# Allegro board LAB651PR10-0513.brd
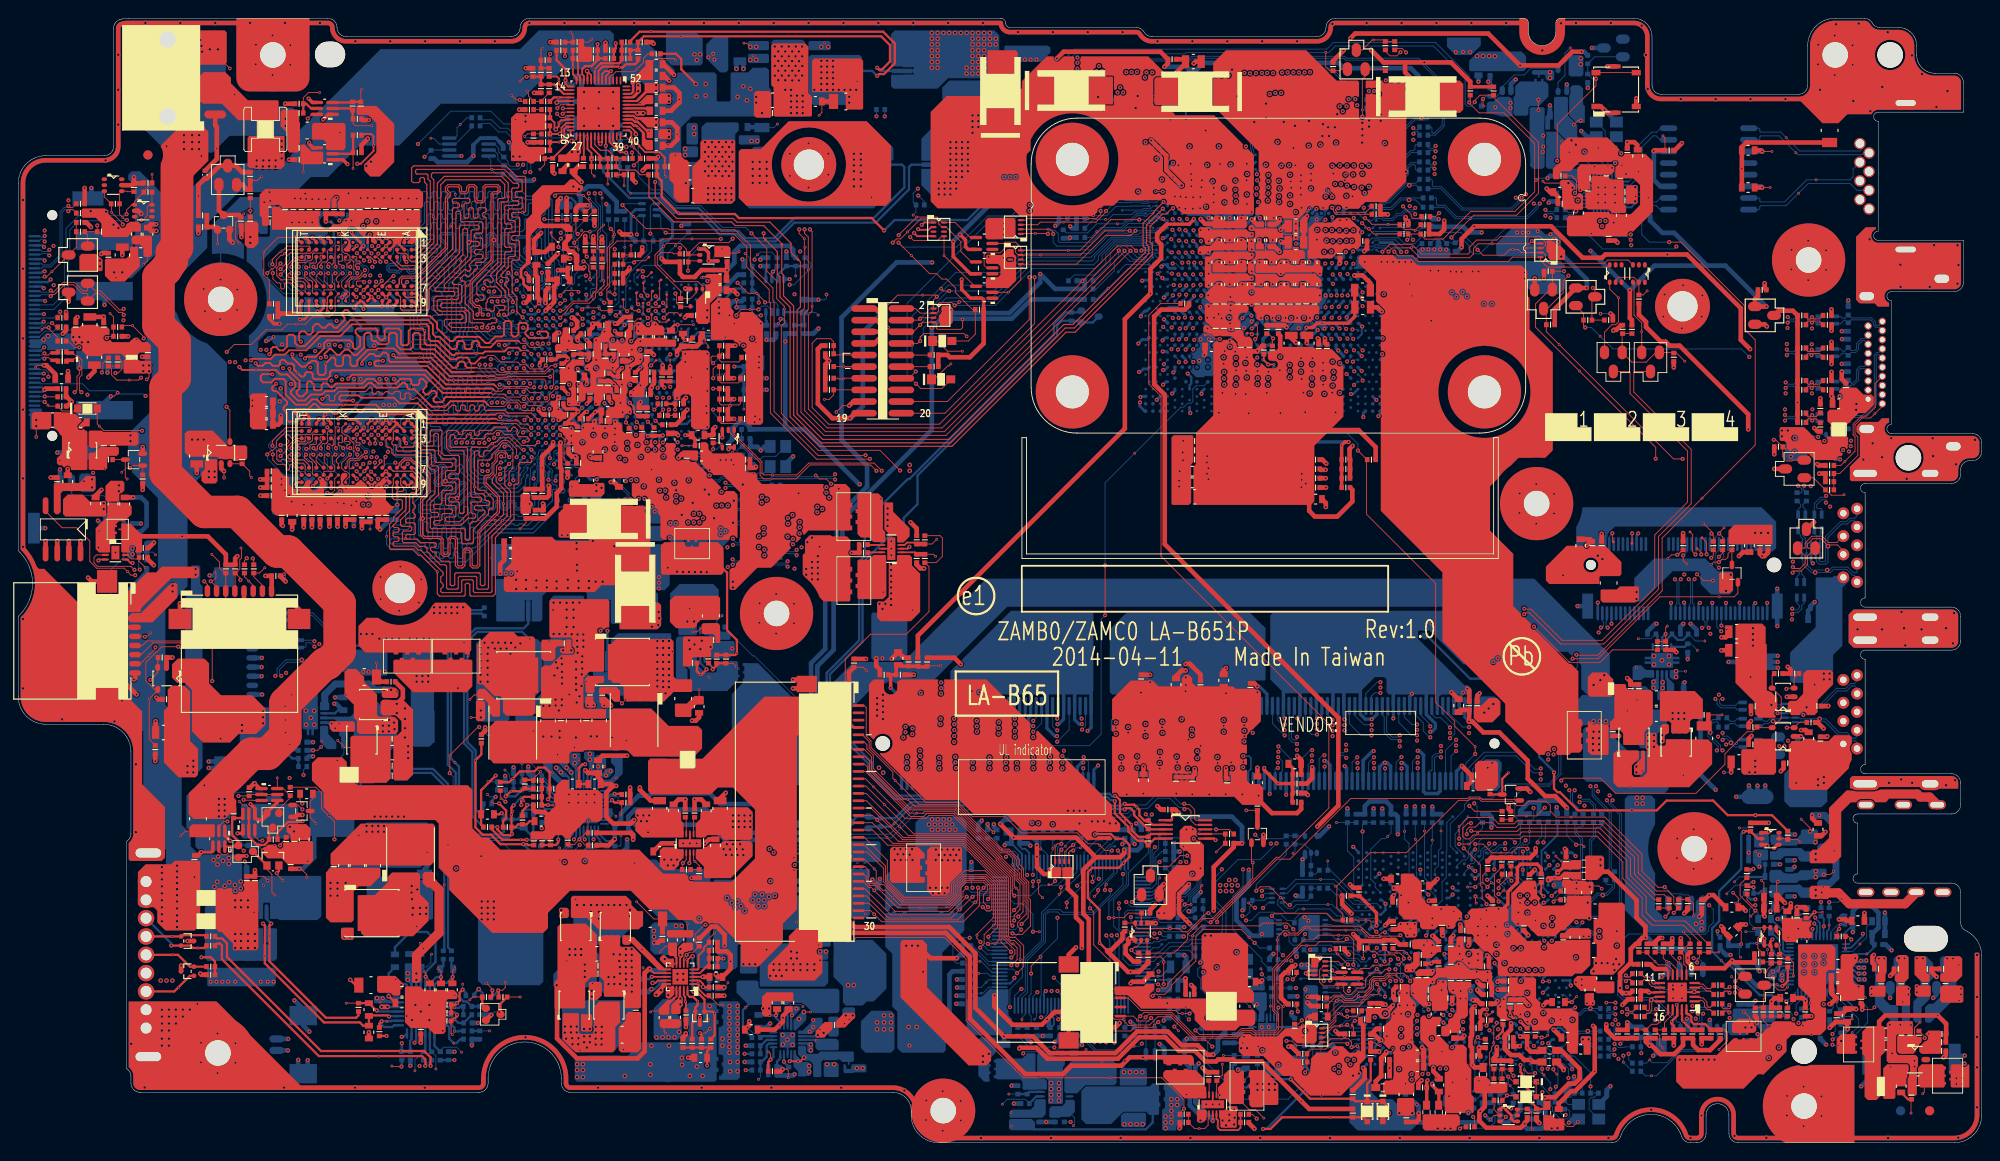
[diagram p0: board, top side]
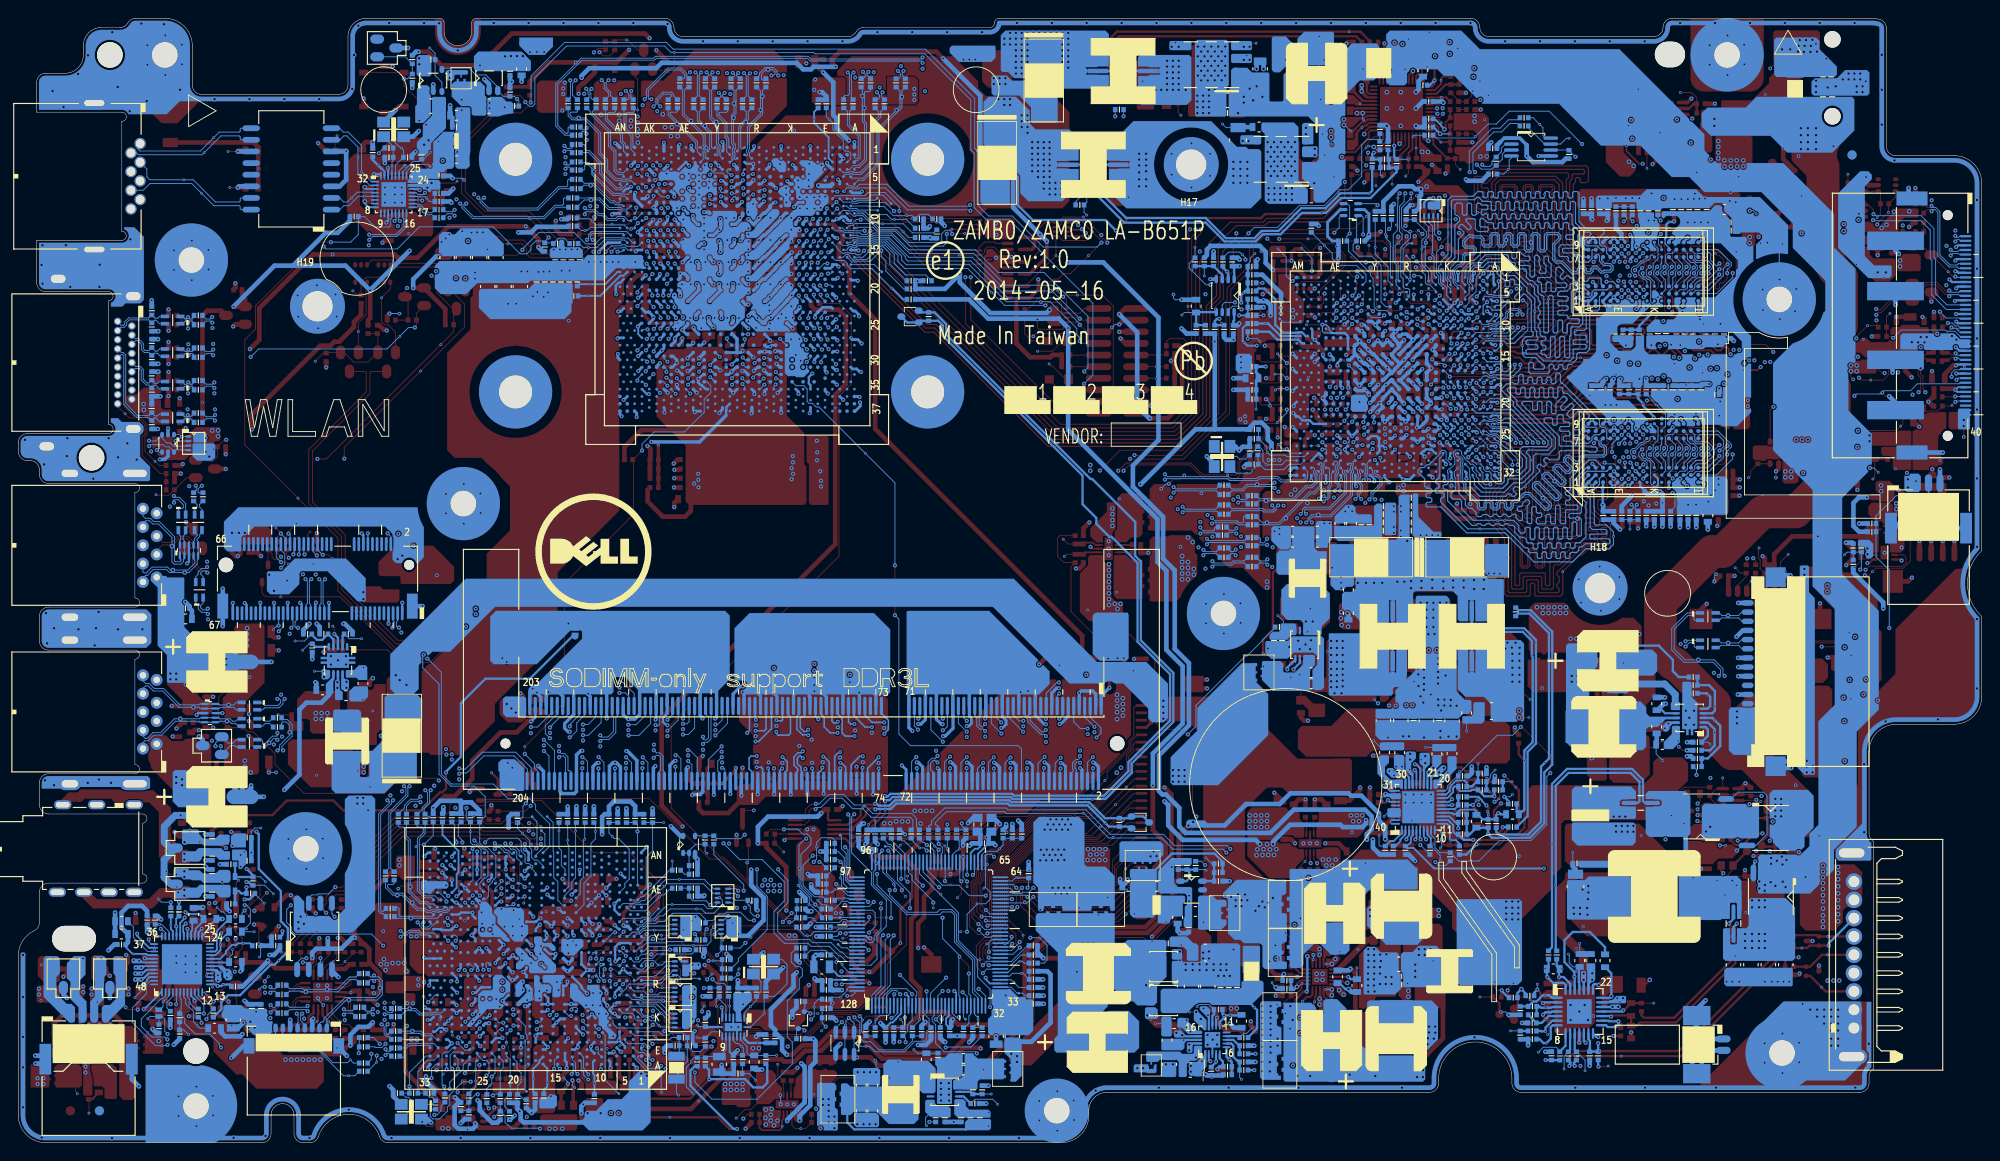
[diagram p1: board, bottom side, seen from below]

Outline 214.4 x 122.8 mm; copper layers: TOP, GND1, IN1, VCC, IN2, IN3, GND2, BOTTOM. Coordinates in mm from the lower left corner of the outline.
Outline path: 0,104.8 arc(0.88,106.92) 3,107.8 9.4,107.8 arc(10.11,108.09) 10.4,108.8 10.4,121.71 arc(10.59,122.3) 11.1,122.66 arc(11.54,122.77) 12,122.8 33.8,122.8 arc(34.51,122.51) 34.8,121.8 arc(35.09,121.09) 35.8,120.8 53.8,120.8 arc(54.51,121.09) 54.8,121.8 arc(55.09,122.51) 55.8,122.8 107.3,122.8 arc(107.65,122.65) 107.8,122.3 arc(107.95,121.95) 108.3,121.8 122.07,121.8 arc(122.57,121.67) 122.93,121.3 arc(123.3,120.93) 123.8,120.8 141.8,120.8 arc(142.51,121.09) 142.8,121.8 arc(143.09,122.51) 143.8,122.8 164.4,122.8 arc(164.75,122.65) 164.9,122.3 164.9,121.3 arc(166.4,119.8) 167.9,121.3 167.9,122.3 arc(168.05,122.65) 168.4,122.8 176.4,122.8 arc(177.81,122.21) 178.4,120.8 178.4,115.5 arc(178.69,114.79) 179.4,114.5 194.4,114.5 arc(195.11,114.79) 195.4,115.5 195.4,119.8 arc(196.28,121.92) 198.4,122.8 201.57,122.8 arc(202.07,122.67) 202.43,122.3 arc(202.8,121.93) 203.3,121.8 205.3,121.8 arc(206.71,121.21) 207.3,119.8 207.3,118.8 arc(207.89,117.39) 209.3,116.8 211.4,116.8 arc(212.11,116.51) 212.4,115.8 212.4,112.55 203.1,112.55 arc(202.6,112.05) 203.1,111.55 203.1,99.55 arc(202.6,99.05) 203.1,98.55 212.4,98.55 212.4,93.95 arc(212.11,93.24) 211.4,92.95 204.55,92.95 arc(204.05,92.45) 204.55,91.95 204.55,78.45 arc(204.05,77.95) 204.55,77.45 213.4,77.45 arc(214.11,77.16) 214.4,76.45 214.4,75.5 arc(214.11,74.79) 213.4,74.5 213.1,74.5 arc(212.39,74.2) 212.1,73.5 212.1,73 arc(211.81,72.29) 211.1,72 201.67,72 arc(201.17,71.5) 201.67,71 201.67,59.5 arc(201.17,59) 201.67,58.5 211.1,58.5 arc(211.81,58.2) 212.1,57.5 212.1,54.8 arc(211.81,54.09) 211.1,53.8 201.67,53.8 arc(201.17,53.3) 201.67,52.8 201.67,41.3 arc(201.17,40.8) 201.67,40.3 211.1,40.3 arc(211.81,40) 212.1,39.3 212.1,36.9 arc(211.81,36.19) 211.1,35.9 200.85,35.9 arc(200.35,35.4) 200.85,34.9 200.85,29.35 arc(200.35,28.85) 200.85,28.35 211.1,28.35 arc(211.81,28.06) 212.1,27.35 212.1,24.05 arc(212.26,23.52) 212.67,23.15 arc(213.93,22.04) 214.4,20.43 214.4,3 arc(213.52,0.88) 211.4,0 187.8,0 arc(187.09,0.29) 186.8,1 186.8,3 arc(185.55,4.25) 184.3,3 184.3,1 arc(184.01,0.29) 183.3,0 182.58,0 arc(181.99,0.19) 181.63,0.69 arc(178.3,3.1) 174.97,0.69 arc(174.61,0.19) 174.02,0 100.5,0 arc(98.38,0.88) 97.5,3 97.5,3.5 arc(96.91,4.91) 95.5,5.5 60.3,5.5 arc(59.59,5.79) 59.3,6.5 59.3,7 arc(55.3,11) 51.3,7 51.3,6.5 arc(51.01,5.79) 50.3,5.5 13.3,5.5 arc(12.59,5.79) 12.3,6.5 12.3,7.23 arc(12.17,7.73) 11.8,8.1 11.8,32.9 arc(12.17,33.27) 12.3,33.77 12.3,42.7 arc(11.42,44.82) 9.3,45.7 3,45.7 arc(0.88,46.58) 0,48.7 0,57.49 arc(1.55,61.07) 0,64.65 0,104.8

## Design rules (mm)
net group 11/16: nets USB20_MINI_N1 USB20_MINI_P1
net group 21: nets +FBA_VREF2 +FBA_VREF3
net group APU_DP2_0: nets APU_DP2_N0 APU_DP2_P0
net group APU_DP2_1: nets APU_DP2_N1 APU_DP2_P1
net group APU_DP2_2: nets APU_DP2_N2 APU_DP2_P2
net group APU_DP2_3: nets APU_DP2_N3 APU_DP2_P3
net group CSI: nets CSIN CSIP
net group DDR_8/12_25: nets MEM_MA_EVENT# MEM_MA_RST#
net group DIFFPAIR3: nets EC_SMB_CK1_R EC_SMB_DA1_R
net group DP2_TX0_R: nets DP2_TXN0_R DP2_TXP0_R
net group DP2_TX1_R: nets DP2_TXN1_R DP2_TXP1_R
net group DP2_TX2_R: nets DP2_TXN2_R DP2_TXP2_R
net group DP2_TX3_R: nets DP2_TXN3_R DP2_TXP3_R
net group FCH_S0: nets FCH_SCLK0 FCH_SDATA0
net group FCH_S1: nets FCH_SCLK1 FCH_SDATA1
net group FCH_S1-TP: nets FCH_SCLK1_TP FCH_SDATA1_TP
net group FCH_S4: nets FCH_SCLK4 FCH_SDATA4
net group ISEN1: nets ISEN1N ISEN1P
net group ISENA1: nets ISENA1N ISENA1P
net group MDI0: nets MDI0+ MDI0-
net group MDI1: nets MDI1+ MDI1-
net group MDO0: nets MDO0+ MDO0-
net group MDO1: nets MDO1+ MDO1-
net group PCIE_CALR: nets PCIE_CALRN PCIE_CALRP
net group PCIE_PRX_DTX_0: nets PCIE_PRX_DTX_N0 PCIE_PRX_DTX_P0
net group PCIE_PRX_DTX_0_C: nets PCIE_PRX_DTX_N0_C PCIE_PRX_DTX_P0_C
net group PCIE_PRX_DTX_1: nets PCIE_PRX_DTX_N1 PCIE_PRX_DTX_P1
net group PCIE_PTX_C_DRX_0: nets PCIE_PTX_C_DRX_N0 PCIE_PTX_C_DRX_P0
net group PCIE_PTX_C_DRX_1: nets PCIE_PTX_C_DRX_N1 PCIE_PTX_C_DRX_P1
net group PCIE_PTX_DRX_0: nets PCIE_PTX_DRX_N0 PCIE_PTX_DRX_P0
net group PCIE_PTX_DRX_1: nets PCIE_PTX_DRX_N1 PCIE_PTX_DRX_P1
net group PEG_GTX_C_HRX_0: nets PEG_GTX_C_HRX_N0 PEG_GTX_C_HRX_P0
net group PEG_GTX_C_HRX_1: nets PEG_GTX_C_HRX_N1 PEG_GTX_C_HRX_P1
net group PEG_GTX_C_HRX_2: nets PEG_GTX_C_HRX_N2 PEG_GTX_C_HRX_P2
net group PEG_GTX_C_HRX_3: nets PEG_GTX_C_HRX_N3 PEG_GTX_C_HRX_P3
net group PEG_GTX_C_HRX_4: nets PEG_GTX_C_HRX_N4 PEG_GTX_C_HRX_P4
net group PEG_GTX_C_HRX_5: nets PEG_GTX_C_HRX_N5 PEG_GTX_C_HRX_P5
net group PEG_GTX_C_HRX_6: nets PEG_GTX_C_HRX_N6 PEG_GTX_C_HRX_P6
net group PEG_GTX_C_HRX_7: nets PEG_GTX_C_HRX_N7 PEG_GTX_C_HRX_P7
net group PEG_GTX_HRX_0: nets PEG_GTX_HRX_N0 PEG_GTX_HRX_P0
net group PEG_GTX_HRX_1: nets PEG_GTX_HRX_N1 PEG_GTX_HRX_P1
net group PEG_GTX_HRX_2: nets PEG_GTX_HRX_N2 PEG_GTX_HRX_P2
net group PEG_GTX_HRX_3: nets PEG_GTX_HRX_N3 PEG_GTX_HRX_P3
net group PEG_GTX_HRX_4: nets PEG_GTX_HRX_N4 PEG_GTX_HRX_P4
net group PEG_GTX_HRX_5: nets PEG_GTX_HRX_N5 PEG_GTX_HRX_P5
net group PEG_GTX_HRX_6: nets PEG_GTX_HRX_N6 PEG_GTX_HRX_P6
net group PEG_GTX_HRX_7: nets PEG_GTX_HRX_N7 PEG_GTX_HRX_P7
net group PEG_HTX_C_GRX_0: nets PEG_HTX_C_GRX_N0 PEG_HTX_C_GRX_P0
net group PEG_HTX_C_GRX_1: nets PEG_HTX_C_GRX_N1 PEG_HTX_C_GRX_P1
net group PEG_HTX_C_GRX_2: nets PEG_HTX_C_GRX_N2 PEG_HTX_C_GRX_P2
net group PEG_HTX_C_GRX_3: nets PEG_HTX_C_GRX_N3 PEG_HTX_C_GRX_P3
net group PEG_HTX_C_GRX_4: nets PEG_HTX_C_GRX_N4 PEG_HTX_C_GRX_P4
net group PEG_HTX_C_GRX_5: nets PEG_HTX_C_GRX_N5 PEG_HTX_C_GRX_P5
net group PEG_HTX_C_GRX_6: nets PEG_HTX_C_GRX_N6 PEG_HTX_C_GRX_P6
net group PEG_HTX_C_GRX_7: nets PEG_HTX_C_GRX_N7 PEG_HTX_C_GRX_P7
net group PEG_HTX_GRX_0: nets PEG_HTX_GRX_N0 PEG_HTX_GRX_P0
net group PEG_HTX_GRX_1: nets PEG_HTX_GRX_N1 PEG_HTX_GRX_P1
net group PEG_HTX_GRX_2: nets PEG_HTX_GRX_N2 PEG_HTX_GRX_P2
net group PEG_HTX_GRX_3: nets PEG_HTX_GRX_N3 PEG_HTX_GRX_P3
net group PEG_HTX_GRX_4: nets PEG_HTX_GRX_N4 PEG_HTX_GRX_P4
net group PEG_HTX_GRX_5: nets PEG_HTX_GRX_N5 PEG_HTX_GRX_P5
net group PEG_HTX_GRX_6: nets PEG_HTX_GRX_N6 PEG_HTX_GRX_P6
net group PEG_HTX_GRX_7: nets PEG_HTX_GRX_N7 PEG_HTX_GRX_P7
net group SATA_PRX_DTX_0: nets SATA_PRX_DTX_N0 SATA_PRX_DTX_P0
net group SATA_PRX_DTX_0_C: nets SATA_PRX_DTX_N0_C SATA_PRX_DTX_P0_C
net group SATA_PRX_DTX_0_R: nets SATA_PRX_DTX_N0_R SATA_PRX_DTX_P0_R
net group SATA_PRX_DTX_0_RC: nets SATA_PRX_DTX_N0_RC SATA_PRX_DTX_P0_RC
net group SATA_PTX_DRX_0: nets SATA_PTX_DRX_N0 SATA_PTX_DRX_P0
net group SATA_PTX_DRX_0_C: nets SATA_PTX_DRX_N0_C SATA_PTX_DRX_P0_C
net group SATA_PTX_DRX_0_R: nets SATA_PTX_DRX_N0_R SATA_PTX_DRX_P0_R
net group SATA_PTX_DRX_0_RC: nets SATA_PTX_DRX_N0_RC SATA_PTX_DRX_P0_RC
net group STAT-CTL: nets SATA_CALRN SATA_CALRP
net group TMDS_L_TX0: nets TMDS_L_TX0N TMDS_L_TX0P
net group TMDS_L_TX1: nets TMDS_L_TX1N TMDS_L_TX1P
net group TMDS_L_TX2: nets TMDS_L_TX2N TMDS_L_TX2P
net group TMDS_L_TXC: nets TMDS_L_TXCN TMDS_L_TXCP
net group TMDS_TX0: nets TMDS_TX0N TMDS_TX0P
net group TMDS_TX1: nets TMDS_TX1N TMDS_TX1P
net group TMDS_TX2: nets TMDS_TX2N TMDS_TX2P
net group TMDS_TXC: nets TMDS_TXCN TMDS_TXCP
net group UMI_ATX_C_FRX_0: nets UMI_ATX_C_FRX_N0 UMI_ATX_C_FRX_P0
net group UMI_ATX_C_FRX_1: nets UMI_ATX_C_FRX_N1 UMI_ATX_C_FRX_P1
net group UMI_ATX_C_FRX_2: nets UMI_ATX_C_FRX_N2 UMI_ATX_C_FRX_P2
net group UMI_ATX_C_FRX_3: nets UMI_ATX_C_FRX_N3 UMI_ATX_C_FRX_P3
net group UMI_ATX_FRX_0: nets UMI_ATX_FRX_N0 UMI_ATX_FRX_P0
net group UMI_ATX_FRX_1: nets UMI_ATX_FRX_N1 UMI_ATX_FRX_P1
net group UMI_ATX_FRX_2: nets UMI_ATX_FRX_N2 UMI_ATX_FRX_P2
net group UMI_ATX_FRX_3: nets UMI_ATX_FRX_N3 UMI_ATX_FRX_P3
net group UMI_FTX_ARX_0: nets UMI_FTX_ARX_N0 UMI_FTX_ARX_P0
net group UMI_FTX_ARX_1: nets UMI_FTX_ARX_N1 UMI_FTX_ARX_P1
net group UMI_FTX_ARX_2: nets UMI_FTX_ARX_N2 UMI_FTX_ARX_P2
net group UMI_FTX_ARX_3: nets UMI_FTX_ARX_N3 UMI_FTX_ARX_P3
net group UMI_FTX_C_ARX_0: nets UMI_FTX_C_ARX_N0 UMI_FTX_C_ARX_P0
net group UMI_FTX_C_ARX_1: nets UMI_FTX_C_ARX_N1 UMI_FTX_C_ARX_P1
net group UMI_FTX_C_ARX_2: nets UMI_FTX_C_ARX_N2 UMI_FTX_C_ARX_P2
net group UMI_FTX_C_ARX_3: nets UMI_FTX_C_ARX_N3 UMI_FTX_C_ARX_P3
net group USB2P0_3: nets USB2P0_N3 USB2P0_P3
net group USB2P10_2: nets USB2P10_N2 USB2P10_P2
net group USB2P10_2_R: nets USB2P10_N2_R USB2P10_P2_R
net group USB2P13_1: nets USB2P13_N1 USB2P13_P1
net group USB2P13_1_R: nets USB2P13_N1_R USB2P13_P1_R
net group USB3P0R2: nets USB3P0RN2 USB3P0RP2
net group USB3P0R2_R: nets USB3P0RN2_R USB3P0RP2_R
net group USB3P0T2: nets USB3P0TN2 USB3P0TP2
net group USB3P0T2_C: nets USB3P0TN2_C USB3P0TP2_C
net group USB3P0T2_R: nets USB3P0TN2_R USB3P0TP2_R
net group USB3P3R1: nets USB3P3RN1 USB3P3RP1
net group USB3P3R1_R: nets USB3P3RN1_R USB3P3RP1_R
net group USB3P3T1: nets USB3P3TN1 USB3P3TP1
net group USB3P3T1_C: nets USB3P3TN1_C USB3P3TP1_C
net group USB3P3T1_R: nets USB3P3TN1_R USB3P3TP1_R
net group USB20: nets USB20_N9 USB20_P9
net group USB20_CAM_7_R: nets USB20_CAM_N7_R USB20_CAM_P7_R
net group USB20_CR_6_R: nets USB20_CR_N6_R USB20_CR_P6_R
net group USB20_JUSB3_2_R: nets USB20_JUSB3_N2_R USB20_JUSB3_P2_R
net group USBSS_CALR: nets USBSS_CALRN USBSS_CALRP
net group VGACS_10_25: nets M_CS#0 M_CS#1
net group 8: nets AUD_HP_OUT_L_CN AUD_HP_OUT_R_CN HPOUT-L HPOUT-R LINE-IN-L LINE-IN-R MIC_IN MIC_IN_R RING2 RING2_R
net group 12: nets ALLOW_STOP CLK_CALRN CLK_SMB CLK_USB30_48M DP_AUX_ZVSS DP_STEREOSYNC MIC_DATA
net group CLK: nets 25M_X1 25M_X2 CLK_X1 CLK_X2 PCH_X1 PCH_X1_R XTALIN XTALOUT XTLI XTLO
net group CLK-1: nets CLK_LAN_25M CLK_LAN_25M_R LAN_X1 LAN_X1_R VGA_X1 VGA_X1_R
net group DDRADD_8/12_30_25: nets DDRA_CKE0 DDRA_CKE1 DDRA_ODT0 DDRA_ODT1 DDRA_SBS0# DDRA_SBS1# DDRA_SBS2# DDRA_SCAS# DDRA_SCS0# DDRA_SCS1# DDRA_SMA0 DDRA_SMA1 DDRA_SMA2 DDRA_SMA3 DDRA_SMA4 DDRA_SMA5 DDRA_SMA6 DDRA_SMA7 DDRA_SMA8 DDRA_SMA9 DDRA_SMA10 DDRA_SMA11 DDRA_SMA12 DDRA_SMA13 DDRA_SMA14 DDRA_SMA15 DDRA_SRAS# DDRA_SWE#
net group DDRCLK_13(20)_30_25: nets DDRA_CLK0 DDRA_CLK0# DDRA_CLK1 DDRA_CLK1#
net group DDRD0_8/12_30_25: nets DDRA_SDM0 DDRA_SDM2 DDRA_SDM4 DDRA_SDM6 DDRA_SDQ0 DDRA_SDQ1 DDRA_SDQ2 DDRA_SDQ3 DDRA_SDQ4 DDRA_SDQ5 DDRA_SDQ6 DDRA_SDQ7 DDRA_SDQ16 DDRA_SDQ17 DDRA_SDQ18 DDRA_SDQ19 DDRA_SDQ20 DDRA_SDQ21 DDRA_SDQ22 DDRA_SDQ23 DDRA_SDQ32 DDRA_SDQ33 DDRA_SDQ34 DDRA_SDQ35 DDRA_SDQ36 DDRA_SDQ37 DDRA_SDQ38 DDRA_SDQ39 DDRA_SDQ48 DDRA_SDQ49 DDRA_SDQ50 DDRA_SDQ51 DDRA_SDQ52 DDRA_SDQ53 DDRA_SDQ54 DDRA_SDQ55
net group DDRD1_8/12_30_25: nets DDRA_SDM1 DDRA_SDM3 DDRA_SDM5 DDRA_SDM7 DDRA_SDQ8 DDRA_SDQ9 DDRA_SDQ10 DDRA_SDQ11 DDRA_SDQ12 DDRA_SDQ13 DDRA_SDQ14 DDRA_SDQ15 DDRA_SDQ24 DDRA_SDQ25 DDRA_SDQ26 DDRA_SDQ27 DDRA_SDQ28 DDRA_SDQ29 DDRA_SDQ30 DDRA_SDQ31 DDRA_SDQ40 DDRA_SDQ41 DDRA_SDQ42 DDRA_SDQ43 DDRA_SDQ44 DDRA_SDQ45 DDRA_SDQ46 DDRA_SDQ47 DDRA_SDQ56 DDRA_SDQ57 DDRA_SDQ58 DDRA_SDQ59 DDRA_SDQ60 DDRA_SDQ61 DDRA_SDQ62 DDRA_SDQ63
net group DDRDQS_11/16_30_25: nets DDRA_SDQS0 DDRA_SDQS0# DDRA_SDQS1 DDRA_SDQS1# DDRA_SDQS2 DDRA_SDQS2# DDRA_SDQS3 DDRA_SDQS3# DDRA_SDQS4 DDRA_SDQS4# DDRA_SDQS5 DDRA_SDQS5# DDRA_SDQS6 DDRA_SDQS6# DDRA_SDQS7 DDRA_SDQS7#
net group EDP: nets APU_EDP0_AUXN APU_EDP0_AUXP APU_EDP0_TXN0 APU_EDP0_TXN1 APU_EDP0_TXP0 APU_EDP0_TXP1 EDP0_AUXN_C EDP0_AUXP_C EDP0_TXN0_C EDP0_TXN1_C EDP0_TXP0_C EDP0_TXP1_C
net group HDA: nets HDA_BITCLK HDA_BITCLK_AUDIO HDA_RST# HDA_RST_AUDIO# HDA_SDIN0 HDA_SDOUT HDA_SDOUT_AUDIO HDA_SYNC HDA_SYNC_AUDIO
net group KB: nets KSI0 KSI1 KSI2 KSI3 KSI4 KSI5 KSI6 KSI7 KSO0 KSO1 KSO2 KSO3 KSO4 KSO5 KSO6 KSO7 KSO8 KSO9 KSO10 KSO11 KSO12 KSO13 KSO14 KSO15 KSO16
net group LPC: nets LPC_AD0 LPC_AD1 LPC_AD2 LPC_AD3 LPC_FRAME#
net group LPC-CLK: nets CLK_EC33M CLK_PCI_EC LPC_CLK1 PCI_CLK1 PCI_CLK3 PCI_CLK4
net group RTC: nets 32K_X1 32K_X2 EC_CRY2 FCH_RTCX1 RTC_CLK
net group SATA: nets SATA_RX_N0 SATA_RX_P0 SATA_TX_N0 SATA_TX_P0
net group SMBUS: nets APU_HDMI_CLK APU_HDMI_DATA CPU_DPB_CTRLCLK_R CPU_DPB_CTRLDAT_R EC_SMB_CK1 EC_SMB_CK2 EC_SMB_CK2_R EC_SMB_DA1 EC_SMB_DA2 EC_SMB_DA2_R FCH_SCLK1_TP_R FCH_SCLK4_R FCH_SDATA1_TP_R FCH_SDATA4_R VGA_SMB_CK3 VGA_SMB_DA3
net group SPI: nets EC_SPI_CLK EC_SPI_CS1# EC_SPI_MISO EC_SPI_MOSI FCH_SPI_CLK FCH_SPI_CS1# FCH_SPI_MISO FCH_SPI_MISO_R FCH_SPI_MOSI FCH_SPI_MOSI_R FCH_SPI_WP#
net group SRCCLK: nets CLK_PCIE_LAN CLK_PCIE_LAN# CLK_PCIE_MINI1 CLK_PCIE_MINI1# CLK_PCIE_MINI1#_R CLK_PCIE_MINI1_R CLK_PCIE_VGA#_R CLK_PCIE_VGA_R
net group USB-CTL: nets USB_RCOMP
net group VGAADD_10_25: nets M_BA0 M_BA1 M_BA2 M_CAS#0 M_CAS#1 M_CKE0 M_CKE1 M_MA0 M_MA1 M_MA2 M_MA3 M_MA4 M_MA5 M_MA6 M_MA7 M_MA8 M_MA9 M_MA10 M_MA11 M_MA12 M_MA13 M_MA14 M_MA15 M_RAS#0 M_RAS#1 M_WE#0 M_WE#1 VRAM_ODT0 VRAM_ODT1
net group VGADATA_10/12_25: nets M_DA0 M_DA1 M_DA2 M_DA3 M_DA4 M_DA5 M_DA6 M_DA7 M_DA8 M_DA9 M_DA10 M_DA11 M_DA12 M_DA13 M_DA14 M_DA15 M_DA16 M_DA17 M_DA18 M_DA19 M_DA20 M_DA21 M_DA22 M_DA23 M_DA24 M_DA25 M_DA26 M_DA27 M_DA28 M_DA29 M_DA30 M_DA31 M_DA32 M_DA33 M_DA34 M_DA35 M_DA36 M_DA37 M_DA38 M_DA39 M_DA40 M_DA41 M_DA42 M_DA43 M_DA44 M_DA45 M_DA46 M_DA47 M_DA48 M_DA49 M_DA50 M_DA51 M_DA52 M_DA53 M_DA54 M_DA55 M_DA56 M_DA57 M_DA58 M_DA59 M_DA60 M_DA61 M_DA62 M_DA63 M_DQM0 M_DQM1 M_DQM2 M_DQM3 M_DQM4 M_DQM5 M_DQM6 M_DQM7
net group W4: nets APU_ALERT# APU_ALLOW_STOP APU_DBRDY APU_DBREQ# APU_PCIE_RST# APU_PCIE_RST#_C APU_PROCHOT# APU_PROCHOT#_R APU_PWRGD APU_PWRGD_R APU_RST# APU_RST#_R APU_SIC APU_SID APU_SVC APU_SVD APU_SVT APU_TCK APU_TDI APU_TDO APU_TEST14 APU_TEST15 APU_TEST16 APU_TEST17 APU_TEST18 APU_TEST19 APU_TEST20 APU_TEST24 APU_TEST25_H APU_TEST25_L APU_TEST28_H APU_TEST28_L APU_TEST31 APU_THERMTRIP# APU_TMS APU_TRST# DP_ENBKL DP_ENVDD DP_INT_PWM JTAG_TCK JTAG_TDI JTAG_TDO JTAG_TMS JTAG_TRSTB KB_RST# MIC_CLK MIC_CLK_C ON/OFF PBTN_OUT# PLT_RST# PM_SLP_S3# PM_SLP_S5# PXS_RST# SERIRQ SUSCLK SUSCLK_R SUSP SUSP# SYS_RESET# SYSON SYSON# TEST0 TEST1 TEST2 TESTEN THM_ALERT# TP_CLK USB_OC0# USB_OC1# USB_OC2# USB_OC3# USB_OC5# VCIN0_PH VCIN0_PH2 VCIN1_PH VGA_PWRGD VGATE VR_ON WD_PWRGD WL_OFF#
net group W5: nets APU_VDD_SEN_H APU_VDD_SEN_L APU_VDDNB_SEN_H
net group W8: nets APU_COREYYPE MA_ZVDDIO P_ZVDDP P_ZVSS
net group W15: nets +FBA_VREF0 +FBA_VREF1 +MA_VREF_DQ +MEM_VREF +VREF_CA
net group W40S20: nets INT-SPK-L+ INT-SPK-L- INT-SPK-R+ INT-SPK-R- SPK_L1-_CONN SPK_L2+_CONN SPK_R1-_CONN SPK_R2+_CONN
nets with their own width: min track width 0.254; nets +1.1VALWP +1.5VSP_ON +1.35VGPUP +1.35VP +3VALW_15 +5VALWP +APU_CORE +APU_CORE_NB +LAN_IO +MPLL_PVDD +SPLL_PVDD +SPLL_VDDC +TSVDD +VCCP_D +VCOIN +VCOIN_RTC +VDDAN_11_USB_S +VDDAN_33_HWM +VDDBT_RTC +VDDCR_11_USB +VDDIO_AZ +VDDPL_11_SYS_S +VDDXL_3.3V +VGA_PCIEP CS1 CS2 ISEN1 ISEN1N-1 ISEN2 ISENA1N-1 LINE1-VREFO-L LINE1-VREFO-R REMOTE1+ REMOTE1- REMOTE2+ REMOTE2- VSUM+ VSUM-
nets with their own width: min track width 0.508; nets +1.1VALW +1.1VS +1.5V_D +1.05VS +1.5VS +1.05VSP +1.5VSP +1.05VSP_B+ +1.8VGS +1.8VS +1.35V +1.35V_MEM_GFX +1.35VGPUP_B+ +3VALW +3VALW_EC +3VALWP +3VGS +3VLP +3VS +3VS_CAM +3VS_TOUCH +5VALW +5VS +5VS_KBL +A_VCC +CODEC_AVDD2 +DP_VDDC +DP_VDDR +EC_VCCA +INV_PWR_SRC +MA_VREFDQ +MIC2-VREFO +MVREFDA +RTCBATT +V18R +V_TP +VDD_CT +VDD_TOUCH +VDDAN_11_SSUSB +VDDCR_1.1V +VDDIO_33_PCIGP +VDDIO_33_S +VDDPL_33_PCIE +VDDPL_33_SATA +VDDPL_33_SSUSB_S +VDDPL_33_SYS +VDDPL_33_USB_S +VDDR3 +VGA_CORE +VGA_PCIE B+ ECAGND GND GNDA LINE1-L LINE1-R
nets with their own width: min track width 0.635; nets +FAN_POWER BST_1.35V BST_3V BST_5V BST_+1.05VSP BST_+1.35VGPUP BST_CHGA
nets with their own width: min track width 0.762; nets +1.1VS_CKVDD +5V_PVDD +5VA +VDDAN_33_USB +VDDCR_11_SSUSB LG_5V LGATE1 LX_3V LX_5V UG_3V UG_5V UGATE1
nets with their own width: min track width 1.016; nets +0.675VS +0.675VSP +3VS_WLAN_NGFF +FCH_VDD_11_SSUSB_S +LAN_VDD33 +MVREFSA +VDISPLAY_VCC LG_3V LG_+1.05VSP LG_+1.35VGPUP LGATE2 LX_1.1V LX_1.5V LX_1.8V LX_CHG LX_PCIE UG_+1.05VSP UG_+1.35VGPUP UGATE2 UGATE_NB1
nets with their own width: min track width 1.27; nets +5V_HDD +VDDAN_11_PCIE
nets with their own width: min track width 1.524; nets +AVDD_SATA +BIF_VDDC +INV_PWR_SRC_R +LAN_REGOUT +LAN_VDD10 +LAN_VDD33_UL2 +LAN_VDD33_UL3 +LAN_VDDREG +VCC_VDDCR_11
nets with their own width: min track width 2.032; nets +5V_USB_PWR1 +5V_USB_PWR2 +5V_USB_PWR3 +LCDVDD +LCDVDD_CONN
nets with their own width: min track width 3.556; nets +VDDCI

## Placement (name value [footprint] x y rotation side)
C5  22U_0805_6.3V6M  [C_0805]  137.85 7.71 90 bottom
C6  0.1U_0402_16V7K  [C_0402]  136.33 9.53 270 bottom
C7  0.1U_0402_16V7K  [C_0402]  135.82 15.98 90 bottom
C8  0.1U_0402_16V7K  [C_0402]  139.38 12.68 90 bottom
C9  0.1U_0402_16V7K  [C_0402]  134.8 15.98 90 bottom
C10  2.2U_0603_6.3V6K  [C_0603]  134.04 9.52 270 bottom
C11  12P_0402_50V8J  [C_0402]  133.79 15.98 90 bottom
C12  12P_0402_50V8J  [C_0402]  132.77 15.98 90 bottom
C14  5P_0402_50V8C  [C_0402]  138.87 16.9 270 bottom
C15  10P_0402_50V8J  [C_0402]  135.36 7.55 0 bottom
C17  0.1U_0402_16V7K  [C_0402]  150.3 113.01 90 bottom
C18  0.1U_0402_16V7K  [C_0402]  149.28 113.01 90 bottom
C19  0.1U_0402_16V7K  [C_0402]  148.27 113.01 90 bottom
C20  0.1U_0402_16V7K  [C_0402]  147.25 113.01 90 bottom
C29  1000P_0402_50V7K  [C_0402]  144.51 73.59 0 top
C30  0.1U_0402_16V7K  [C_0402]  145.42 74.6 180 top
C53  27P_0402_50V8J  [C_0402]  173.21 89.84 0 top
C54  27P_0402_50V8J  [C_0402]  153.14 99.24 0 top
C55  27P_0402_50V8J  [C_0402]  155.97 98.2 180 bottom
C57  0.22U_0402_10V4Z  [C_0402]  154.24 94.47 270 bottom
C58  22U_0805_6.3V6M  [C_0805]  167.58 95.83 90 bottom
C59  22U_0805_6.3V6M  [C_0805]  164.02 95.83 90 bottom
C60  22U_0805_6.3V6M  [C_0805]  165.8 95.83 90 bottom
C61  0.22U_0402_10V4Z  [C_0402]  154.88 95.96 90 bottom
C62  0.22U_0402_10V4Z  [C_0402]  155.77 95.96 90 bottom
C63  180P_0402_50V8J  [C_0402]  153.99 95.96 90 bottom
C64  180P_0402_50V8J  [C_0402]  153.1 95.96 90 bottom
C65  180P_0402_50V8J  [C_0402]  156.02 94.47 270 bottom
C66  180P_0402_50V8J  [C_0402]  156.91 94.47 270 bottom
C68  22U_0805_6.3V6M  [C_0805]  162.25 95.83 90 bottom
C69  22U_0805_6.3V6M  [C_0805]  163.13 94.35 270 bottom
C70  22U_0805_6.3V6M  [C_0805]  161.36 94.35 270 bottom
C71  22U_0805_6.3V6M  [C_0805]  159.58 94.35 270 bottom
C72  0.22U_0402_10V4Z  [C_0402]  155.13 94.47 270 bottom
C73  0.22U_0402_10V4Z  [C_0402]  157.8 94.47 270 bottom
C74  4.7U_0603_6.3V6K  [C_0603]  141.29 96.87 270 top
C75  0.22U_0402_6.3V6K  [C_0402]  146.36 98.48 0 top
C76  3300P_0402_50V7K  [C_0402]  144.33 97.55 270 top
C77  22U_0805_6.3V6M  [C_0805]  145.95 91.24 0 top
C78  22U_0805_6.3V6M  [C_0805]  145.93 93.11 0 top
C79  22U_0805_6.3V6M  [C_0805]  140.36 98.33 180 top
C80  22U_0805_6.3V6M  [C_0805]  140.36 100.1 180 top
C81  22U_0805_6.3V6M  [C_0805]  127.46 118.08 0 top
C82  4.7U_0603_6.3V6K  [C_0603]  140.96 70.29 0 top
C83  4.7U_0603_6.3V6K  [C_0603]  130.99 86.95 180 top
C84  4.7U_0603_6.3V6K  [C_0603]  128.9 73.33 180 top
C85  4.7U_0603_6.3V6K  [C_0603]  128.9 72.06 180 top
C88  22U_0805_6.3V6M  [C_0805]  129.3 70.54 180 top
C89  22U_0805_6.3V6M  [C_0805]  139 86.47 90 top
C90  22U_0805_6.3V6M  [C_0805]  140.71 86.48 90 top
C93  0.22U_0402_10V4Z  [C_0402]  141.2 73.59 0 top
C94  0.22U_0402_10V4Z  [C_0402]  141.2 71.56 0 top
C95  0.22U_0402_10V4Z  [C_0402]  141.2 74.6 0 top
C96  0.22U_0402_10V4Z  [C_0402]  128.91 75.62 180 top
C99  180P_0402_50V8J  [C_0402]  141.2 72.57 0 top
C100  180P_0402_50V8J  [C_0402]  128.91 74.6 180 top
C103  0.22U_0402_10V4Z  [C_0402]  128.91 76.64 180 top
C104  0.22U_0402_10V4Z  [C_0402]  133.54 86.41 90 top
C105  0.22U_0402_10V4Z  [C_0402]  134.43 86.41 90 top
C106  0.22U_0402_10V4Z  [C_0402]  137.6 88.37 90 top
C107  0.22U_0402_10V4Z  [C_0402]  142 86.29 90 top
C108  0.22U_0402_10V4Z  [C_0402]  142.89 86.29 90 top
C109  0.1U_0402_16V4Z  [C_0402]  122.61 51.11 270 top
C110  0.1U_0402_16V4Z  [C_0402]  134.55 50.17 270 top
C111  0.1U_0402_16V4Z  [C_0402]  132.01 39.76 270 top
C112  1U_0402_6.3V6K  [C_0402]  129.09 49.56 90 top
C113  1U_0402_6.3V6K  [C_0402]  128.2 39.02 90 top
C114  1U_0402_6.3V6K  [C_0402]  126.42 39.02 90 top
C115  10U_0603_6.3V6M  [C_0603]  122.87 38.85 90 top
C116  10U_0603_6.3V6M  [C_0603]  131.63 49.78 90 top
C117  10U_0603_6.3V6M  [C_0603]  135.31 38.6 90 top
C118  10U_0603_6.3V6M  [C_0603]  126.42 49.31 90 top
C119  0.1U_0402_16V4Z  [C_0402]  159.32 48.18 270 top
C120  1U_0402_6.3V6K  [C_0402]  159.59 40.11 180 top
C121  4.7U_0603_6.3V6K  [C_0603]  159.57 38.96 180 top
C122  4.7U_0603_6.3V6K  [C_0603]  138.68 41.38 0 top
C123  0.1U_0402_16V4Z  [C_0402]  139.18 40.23 0 top
C124  1000P_0402_50V7K  [C_0402]  139.18 39.22 0 top
C125  4.7U_0603_6.3V6K  [C_0603]  96.07 52.19 90 top
C126  0.1U_0402_16V4Z  [C_0402]  95.87 51.11 0 top
C127  1000P_0402_50V7K  [C_0402]  95 51.11 180 top
C128  2.2U_0603_6.3V6K  [C_0603]  157.29 47.03 90 top
C129  0.1U_0402_16V7K  [C_0402]  158.43 47.27 90 top
C151  0.22U_0402_10V4Z  [C_0402]  141.15 115.29 90 bottom
C152  0.22U_0402_10V4Z  [C_0402]  139.63 113.01 90 bottom
C153  0.22U_0402_10V4Z  [C_0402]  143.44 113.01 90 bottom
C154  0.22U_0402_10V4Z  [C_0402]  142.17 115.29 90 bottom
C155  0.22U_0402_10V4Z  [C_0402]  140.65 113.01 90 bottom
C156  0.22U_0402_10V4Z  [C_0402]  138.36 115.29 90 bottom
C157  0.22U_0402_10V4Z  [C_0402]  139.38 115.29 90 bottom
C158  0.22U_0402_10V4Z  [C_0402]  132.77 115.29 90 bottom
C159  0.22U_0402_10V4Z  [C_0402]  134.3 113.01 90 bottom
C160  0.22U_0402_10V4Z  [C_0402]  135.57 115.29 90 bottom
C161  0.22U_0402_10V4Z  [C_0402]  138.11 113.01 90 bottom
C162  0.22U_0402_10V4Z  [C_0402]  133.79 115.29 90 bottom
C163  0.22U_0402_10V4Z  [C_0402]  136.58 115.29 90 bottom
C164  0.22U_0402_10V4Z  [C_0402]  142.42 113.01 90 bottom
C165  0.22U_0402_10V4Z  [C_0402]  137.09 113.01 90 bottom
C166  0.22U_0402_10V4Z  [C_0402]  135.31 113.01 90 bottom
C343  330P_0402_50V7K  [C_0402]  129.99 7.7 270 top
C344  330P_0402_50V7K  [C_0402]  91.83 64.43 0 top
C348  330P_0402_50V7K  [C_0402]  91.83 65.32 0 top
C349  330P_0402_50V7K  [C_0402]  130.88 7.7 270 top
C935  0.1U_0402_16V4Z  [C_0402]  180.78 86.24 270 top
C936  1000P_0402_50V7K  [C_0402]  89.03 86.16 180 top
C983  0.1U_0402_16V7K  [C_0402]  126.85 2.21 0 top
C986  0.1U_0402_16V7K  [C_0402]  98.1 66.3 270 top
C987  0.1U_0402_16V7K  [C_0402]  134.37 2.21 180 top
C1014  0.1U_0402_16V7K  [C_0402]  98.1 63.35 90 top
C2498  0.1U_0402_10V6K  [C_0402]  125.99 36.38 180 top
C2500  2200P_0402_25V7K  [C_0402]  94.16 35.44 270 bottom
C2502  2200P_0402_25V7K  [C_0402]  123.37 35.18 270 top
C2504  2200P_0402_25V7K  [C_0402]  123.37 33.41 270 top
C2505  2200P_0402_25V7K  [C_0402]  114.99 89.77 90 bottom
C4311  0.1U_0402_16V7K  [C_0402]  153.35 113.01 90 bottom
C4312  0.1U_0402_16V7K  [C_0402]  154.36 113.01 90 bottom
C4313  0.1U_0402_16V7K  [C_0402]  151.31 113.01 90 bottom
C4314  0.1U_0402_16V7K  [C_0402]  152.33 113.01 90 bottom
C4321  0.1U_0402_16V7K  [C_0402]  153.93 110.04 180 bottom
C4322  0.1U_0402_16V7K  [C_0402]  153.93 110.93 180 bottom
CA1  10U_0603_6.3V6M  [C_0603]  190.62 26.85 0 top
CA2  10U_0603_6.3V6M  [C_0603]  190.62 25.58 0 top
CA21  22P_0402_50V8J  [C_0402]  196.78 12.32 270 bottom
CA22  22P_0402_50V8J  [C_0402]  199.04 12.91 270 bottom
CA23  2.2U_0603_6.3V6K  [C_0603]  195.26 25.65 270 bottom
CA24  1U_0402_6.3V6K  [C_0402]  199.52 22.53 180 top
CA25  1U_0402_6.3V6K  [C_0402]  199.45 24.77 270 bottom
CA29  1000P_0402_50V7K  [C_0402]  203.59 18.98 180 top
CA30  1000P_0402_50V7K  [C_0402]  205.75 18.98 180 top
CA31  1000P_0402_50V7K  [C_0402]  208.01 18.98 0 top
CA32  1000P_0402_50V7K  [C_0402]  210.7 18.98 180 top
CA33  100P_0402_50V8J  [C_0402]  193.22 27.82 270 bottom
CA38  1000P_0402_50V7K  [C_0402]  193.22 32.74 90 bottom
CA39  100P_0402_50V8J  [C_0402]  193.22 28.93 90 bottom
CA40  1000P_0402_50V7K  [C_0402]  193.22 31.75 270 bottom
CA51  0.1U_0402_16V7K  [C_0402]  194.22 24.09 90 top
CA53  4.7U_0603_6.3V6K  [C_0603]  199.38 18.09 180 top
CA54  0.1U_0402_16V7K  [C_0402]  201.22 16.13 270 top
CA55  4.7U_0603_6.3V6K  [C_0603]  199.38 16.82 180 top
CA56  0.1U_0402_16V7K  [C_0402]  199.45 15.78 180 top
CA57  4.7U_0603_6.3V6K  [C_0603]  199.7 14.6 270 top
CA58  0.1U_0402_16V7K  [C_0402]  198.56 14.1 270 top
CA59  4.7U_0603_6.3V6K  [C_0603]  193.8 15.8 180 top
CA60  0.1U_0402_16V7K  [C_0402]  195.13 14.74 270 top
CA61  4.7U_0603_6.3V6K  [C_0603]  202.43 22.79 0 bottom
CA62  10U_0603_6.3V6M  [C_0603]  192.78 24.44 0 bottom
CA63  10U_0603_6.3V6M  [C_0603]  203.83 24.19 180 bottom
CA64  10U_0603_6.3V6M  [C_0603]  192.27 12.5 0 bottom
CA65  0.1U_0402_16V7K  [C_0402]  193.21 14.74 270 top
CA67  4.7U_0603_6.3V6K  [C_0603]  191.38 24.44 180 bottom
CA68  4.7U_0603_6.3V6K  [C_0603]  191.38 23.04 180 bottom
CA69  100P_0402_50V8J  [C_0402]  191.45 13.82 90 top
CA71  4.7U_0603_6.3V6K  [C_0603]  193.17 23.87 90 top
CA74  10U_0603_6.3V6M  [C_0603]  191.38 19.74 180 bottom
CC84  0.1U_0402_16V7K  [C_0402]  153.4 103.18 0 bottom
CC85  0.1U_0402_16V7K  [C_0402]  153.4 102.16 0 bottom
CC86  0.1U_0402_16V7K  [C_0402]  153.02 105.21 0 bottom
CC87  0.1U_0402_16V7K  [C_0402]  153.02 104.2 0 bottom
CC88  0.1U_0402_16V7K  [C_0402]  153.02 107.12 0 bottom
CC89  0.1U_0402_16V7K  [C_0402]  153.02 106.23 0 bottom
CC90  0.1U_0402_16V7K  [C_0402]  153.02 109.02 0 bottom
CC91  0.1U_0402_16V7K  [C_0402]  153.02 108.13 0 bottom
CE1  0.1U_0402_16V7K  [C_0402]  112.71 12.58 270 bottom
CE2  0.1U_0402_16V7K  [C_0402]  125.71 17.71 0 bottom
CE3  0.1U_0402_16V7K  [C_0402]  125.71 16.69 0 bottom
CE4  0.1U_0402_16V7K  [C_0402]  119.69 12.58 270 bottom
CE5  1000P_0402_50V7K  [C_0402]  122.64 34.18 270 bottom
CE6  1000P_0402_50V7K  [C_0402]  103.1 15.17 0 bottom
CE7  0.1U_0402_16V7K  [C_0402]  108.44 32.69 0 bottom
CE8  0.1U_0402_16V7K  [C_0402]  106.86 33.25 90 bottom
CE9  100P_0402_50V8J  [C_0402]  104.07 29.85 270 bottom
CE10  22P_0402_50V8J  [C_0402]  118.8 12.58 270 bottom
CE11  0.1U_0402_16V7K  [C_0402]  104.02 17.84 180 bottom
CE14  0.1U_0402_16V7K  [C_0402]  115.75 11.66 90 bottom
CE15  0.1U_0402_16V7K  [C_0402]  121.85 11.66 90 bottom
CE16  4.7U_0805_10V4Z  [C_0805]  125.82 19.21 0 bottom
CE17  20P_0402_50V8  [C_0402]  126.63 20.5 180 bottom
CE18  100P_0402_50V8J  [C_0402]  126.63 23.55 180 bottom
CE20  0.1U_0402_16V7K  [C_0402]  171.38 116.72 270 bottom
CE22  2.2U_0603_6.3V6K  [C_0603]  5.39 71.49 90 top
CE23  1000P_0402_50V7K  [C_0402]  4.25 71.73 90 top
CE24  0.01U_0402_16V7K  [C_0402]  11.54 67.62 0 bottom
CE25  2.2U_0603_6.3V6K  [C_0603]  8.44 69.08 90 top
CE26  1000P_0402_50V7K  [C_0402]  125.25 31.81 0 bottom
CE27  1000P_0402_50V7K  [C_0402]  125.25 30.92 0 bottom
CE29  0.1U_0402_16V7K  [C_0402]  111.18 12.58 270 bottom
CE56  1U_0603_10V6K  [C_0603]  133.72 17.58 0 top
CE57  10U_0603_6.3V6M  [C_0603]  123.63 17.01 90 top
CE58  1U_0402_6.3V6K  [C_0402]  27.67 61.9 0 top
CE59  0.1U_0402_10V6K  [C_0402]  13.19 64.95 0 top
CE60  2200P_0402_25V7K  [C_0402]  13.19 63.94 0 top
CE61  1U_0402_6.3V6K  [C_0402]  127.49 16.18 0 top
CH1  0.1U_0402_16V7K  [C_0402]  170.87 35.89 270 bottom
CH2  0.1U_0402_16V7K  [C_0402]  172.01 35.89 270 bottom
CH3  0.1U_0402_16V7K  [C_0402]  173.36 29.6 270 bottom
CH4  0.1U_0402_16V7K  [C_0402]  174.25 24.69 180 bottom
CH5  0.1U_0402_16V7K  [C_0402]  174.25 25.58 180 bottom
CH6  150P_0402_50V8J  [C_0402]  140.23 27.8 0 bottom
CH7  0.1U_0402_16V7K  [C_0402]  169.98 35.89 270 bottom
CH8  0.1U_0402_16V7K  [C_0402]  172.9 35.89 270 bottom
CH9  0.1U_0402_16V7K  [C_0402]  174.3 29.6 270 bottom
CH10  18P_0402_50V8J  [C_0402]  140.44 10.6 0 bottom
CH11  18P_0402_50V8J  [C_0402]  143.14 10.6 180 bottom
CH12  10P_0402_50V8J  [C_0402]  169.02 5.41 0 bottom
CH13  1U_0402_6.3V6K  [C_0402]  147.68 10.9 90 top
CH14  0.1U_0402_16V7K  [C_0402]  151.57 3.18 270 top
CH15  10P_0402_50V8J  [C_0402]  173.46 5.41 180 bottom
CH16  150P_0402_50V8J  [C_0402]  141.15 29.31 180 bottom
CH17  10P_0402_50V8J  [C_0402]  163 7.98 90 top
CH20  22P_0402_50V8J  [C_0402]  182.3 25.66 90 top
CH23  100P_0402_50V8J  [C_0402]  137.55 19.99 180 bottom
CH25  0.1U_0402_16V7K  [C_0402]  162.33 10.53 0 top
CH26  1U_0402_6.3V6K  [C_0402]  156.44 21 90 top
CH27  0.1U_0402_16V7K  [C_0402]  154.66 25.5 90 top
CH29  1U_0402_6.3V6K  [C_0402]  162.11 13.85 270 top
CH30  22U_0603_6.3V6M  [C_0603]  152.63 28.06 0 top
CH31  2.2U_0402_6.3V6M  [C_0402]  162.33 11.48 0 top
CH32  0.1U_0402_16V7K  [C_0402]  156.44 19.94 270 top
CH33  0.1U_0402_16V7K  [C_0402]  157.51 22.21 0 top
CH34  1U_0402_6.3V6K  [C_0402]  159.67 19.26 0 top
CH35  10U_0603_6.3V6M  [C_0603]  171.62 17.39 270 top
CH36  0.1U_0402_16V7K  [C_0402]  155.49 24.2 270 top
CH37  0.1U_0402_16V7K  [C_0402]  150.99 26.28 180 top
CH39  0.1U_0402_16V7K  [C_0402]  164 14.71 90 top
CH40  0.1U_0402_16V7K  [C_0402]  163.18 16.74 180 top
CH41  1U_0402_6.3V6K  [C_0402]  163.18 17.66 180 top
CH42  22U_0603_6.3V6M  [C_0603]  169.9 11.48 180 top
CH43  2.2U_0603_6.3V6K  [C_0603]  167.49 15.36 0 top
CH44  0.1U_0402_16V7K  [C_0402]  164.39 24.13 270 top
CH45  1U_0402_6.3V6K  [C_0402]  165.01 28.36 90 top
CH46  22U_0603_6.3V6M  [C_0603]  171.25 26.65 90 top
CH50  0.1U_0402_16V7K  [C_0402]  168.71 21.7 90 top
CH51  1U_0402_6.3V6K  [C_0402]  160.99 25.5 90 top
CH52  1U_0402_6.3V6K  [C_0402]  158.42 23.17 180 top
CH53  22U_0603_6.3V6M  [C_0603]  169.98 21.71 90 top
CH56  1U_0402_6.3V6K  [C_0402]  159.87 15.17 0 top
CH57  1U_0402_6.3V6K  [C_0402]  153.66 20.5 180 top
CH58  2.2U_0402_6.3V6M  [C_0402]  155.11 21.06 90 top
CH59  10U_0603_6.3V6M  [C_0603]  152.06 9.58 0 top
CH60  10U_0603_6.3V6M  [C_0603]  152.06 8.31 0 top
CH61  1U_0402_6.3V6K  [C_0402]  149.53 12.44 180 top
CH62  1U_0402_6.3V6K  [C_0402]  151.25 15.66 180 top
CH63  0.1U_0402_16V7K  [C_0402]  151.37 17.01 180 top
CH64  2.2U_0402_6.3V6M  [C_0402]  158.73 12.5 0 top
CH65  0.1U_0402_16V7K  [C_0402]  158.73 14.28 0 top
CH66  2.2U_0402_6.3V6M  [C_0402]  164.76 11.6 90 top
CH67  2.2U_0402_6.3V6M  [C_0402]  153.8 6.02 180 top
CH68  0.1U_0402_16V7K  [C_0402]  155.11 19.75 270 top
CH69  0.1U_0402_16V7K  [C_0402]  153.66 19.55 180 top
CH70  1U_0402_6.3V6K  [C_0402]  159.98 17.13 0 top
CH71  1U_0402_6.3V6K  [C_0402]  159.98 16.18 0 top
CH72  2.2U_0402_6.3V6M  [C_0402]  148.82 7.29 0 top
CH73  0.1U_0402_16V7K  [C_0402]  148.82 9.07 0 top
CH74  10U_0603_6.3V6M  [C_0603]  155.12 5.58 90 top
CH75  0.1U_0402_16V7K  [C_0402]  153.77 18.48 270 top
CH76  0.1U_0402_16V7K  [C_0402]  152.88 18.48 270 top
CH77  2.2U_0402_6.3V6M  [C_0402]  165.79 3.69 270 top
CH78  0.1U_0402_16V7K  [C_0402]  162.92 14.71 90 top
CH79  2.2U_0402_6.3V6M  [C_0402]  169.01 30.27 90 top
CH80  1U_0402_6.3V6K  [C_0402]  154.42 15.8 180 top
CH81  0.1U_0402_16V7K  [C_0402]  155.66 15.8 0 top
CH82  0.1U_0402_16V7K  [C_0402]  154.42 16.69 180 top
CH83  2.2U_0402_6.3V6M  [C_0402]  147.6 14.32 90 top
CH84  0.1U_0402_16V7K  [C_0402]  148.48 14.32 90 top
CH85  2.2U_0402_6.3V6M  [C_0402]  145.48 26.96 180 top
CH86  2.2U_0402_6.3V6M  [C_0402]  169.01 29.34 270 top
CH87  10U_0603_6.3V6M  [C_0603]  156.9 12.82 270 top
CH88  1U_0402_6.3V6K  [C_0402]  156.44 17.25 90 top
CH89  0.1U_0402_16V7K  [C_0402]  158.34 17.25 90 top
CH90  0.1U_0402_16V7K  [C_0402]  157.39 17.25 90 top
CH91  10U_0603_6.3V6M  [C_0603]  143 13.77 180 top
CH92  0.1U_0402_16V7K  [C_0402]  142.88 14.91 180 top
CH466  0.1U_0402_16V4Z  [C_0402]  183.83 25.63 90 top
CI1  220U_6.3V_M  [C_MP6VLPS220MC4R2]  195.52 52.51 0 bottom
CI2  0.1U_0402_16V7K  [C_0402]  196.6 58.35 180 bottom
CI3  0.1U_0402_10V7K  [C_0402]  195.26 70.08 90 bottom
CI4  0.1U_0402_10V7K  [C_0402]  194.24 70.08 90 bottom
CI5  10P_0402_50V8J  [C_0402]  195.94 47.68 0 top
CI6  4.7U_0805_10V4Z  [C_0805]  188.74 41.58 180 top
CI7  0.1U_0402_16V7K  [C_0402]  189.87 43.49 180 top
CI8  220U_6.3V_M  [C_MP6VLPS220MC4R2]  195.52 37.77 0 bottom
CI9  0.1U_0402_16V7K  [C_0402]  196.78 43.41 90 top
CI10  0.1U_0402_10V7K  [C_0402]  186.57 46.41 180 bottom
CI11  0.1U_0402_10V7K  [C_0402]  186.57 45.39 180 bottom
CI12  4.7U_0805_10V4Z  [C_0805]  188.49 55.81 180 top
CI13  0.1U_0402_16V7K  [C_0402]  191.75 51.24 0 top
CI14  0.1U_0402_16V7K  [C_0402]  190.13 47.68 180 top
CI15  0.1U_0402_16V7K  [C_0402]  194.44 51.24 180 top
CI16  10P_0402_50V8J  [C_0402]  193.68 41.46 180 top
CI17  0.1U_0402_16V7K  [C_0402]  195.31 45.9 0 top
CI18  47U_0805_6.3V4Z  [C_0805]  188.49 53.78 180 top
CI26  0.1U_0402_16V7K  [C_0402]  189.87 45.39 180 top
CI40  10U_0603_6.3V6M  [C_0603]  196.84 57.21 180 bottom
CI43  10U_0603_6.3V6M  [C_0603]  195.51 43.43 90 top
CI44  4.7U_0805_10V4Z  [C_0805]  16.69 44.8 180 top
CI45  0.1U_0402_16V7K  [C_0402]  16.64 48.43 180 top
CI46  0.1U_0402_16V7K  [C_0402]  14.95 43.39 270 top
CI47  0.1U_0402_16V7K  [C_0402]  15.26 52.99 0 top
CL3  0.1U_0402_25V6  [C_0402]  168.92 105.59 180 bottom
CL4  4.7U_0603_6.3V6K  [C_0603]  165.86 112.2 0 bottom
CL5  0.1U_0402_25V6  [C_0402]  166.1 110.93 0 bottom
CL6  0.1U_0402_25V6  [C_0402]  173.41 106.05 270 top
CL7  0.1U_0402_25V6  [C_0402]  171.18 105.34 0 top
CL8  0.1U_0402_25V6  [C_0402]  175.9 103.81 180 top
CL9  1U_0402_6.3V4Z  [C_0402]  171.38 104.4 270 top
CL10  0.1U_0402_25V6  [C_0402]  175.9 102.93 180 top
CL12  0.1U_0402_16V7K  [C_0402]  174.94 105.8 270 top
CL13  4.7U_0603_6.3V6K  [C_0603]  175.06 100.58 90 top
CL14  4.7U_0603_6.3V6K  [C_0603]  176.84 107.05 90 top
CL15  0.1U_0402_10V7K  [C_0402]  173.67 99.45 270 top
CL16  0.1U_0402_16V4Z  [C_0402]  168.13 102.54 0 top
CL17  4.7U_0603_6.3V6K  [C_0603]  169.03 103.81 180 top
CL19  0.1U_0402_10V7K  [C_0402]  175.7 107.67 90 top
CL30  0.1U_0402_10V7K  [C_0402]  168 101.02 0 bottom
CL31  0.1U_0402_10V7K  [C_0402]  168 101.91 0 bottom
CL33  100P_1206_2KV8J  [C_1206]  197.8 109.24 90 top
CL36  15P_0402_50V8J  [C_0402]  174.38 107.62 180 bottom
CL37  15P_0402_50V8J  [C_0402]  171.43 107.62 0 bottom
CL38  0.1U_0603_25V7K  [C_0603]  159.44 117.97 270 bottom
CL39  1U_0402_6.3V6K  [C_0402]  160.71 117.48 270 bottom
CL41  0.01U_0402_16V7K  [C_0402]  180.73 108.39 180 top
CLRP1  SHORT PADS  [SHORTPADS]  153.6 55.81 90 bottom
CM4  22U_0603_6.3V6M  [C_0603]  170.62 64.51 90 top
CM5  0.1U_0402_10V7K  [C_0402]  172.9 64.75 90 top
CM6  22U_0603_6.3V6M  [C_0603]  189.03 65.9 270 top
CM7  0.1U_0402_10V7K  [C_0402]  190.18 65.66 270 top
CM9  10P_0402_50V8J  [C_0402]  171.89 64.75 90 top
CM10  10P_0402_50V8J  [C_0402]  191.06 65.66 270 top
CS5  1000P_0402_50V7K  [C_0402]  188.91 14.2 90 bottom
CS6  0.1U_0402_25V6K  [C_0402]  187.89 14.2 90 bottom
CS7  10U_0805_10V6K  [C_0805]  190.94 14.24 270 bottom
CS27  0.1U_0402_25V6K  [C_0402]  175.7 12.32 270 top
CS30  0.01U_0402_16V7K  [C_0402]  177.58 13.77 180 top
CS31  0.01U_0402_16V7K  [C_0402]  177.17 17.45 180 top
CS32  0.01U_0402_16V7K  [C_0402]  177.58 14.79 180 top
CS33  0.01U_0402_16V7K  [C_0402]  186.06 16.18 180 top
CS34  0.01U_0402_16V7K  [C_0402]  177.17 18.47 180 top
CS35  0.01U_0402_16V7K  [C_0402]  186.06 17.2 180 top
CS36  0.01U_0402_16V7K  [C_0402]  186.06 15.17 180 top
CS37  0.01U_0402_16V7K  [C_0402]  186.06 14.15 180 top
CS38  0.01U_0402_16V7K  [C_0402]  177.58 13.77 180 bottom
CS39  0.01U_0402_16V7K  [C_0402]  177.58 14.79 180 bottom
CS40  0.01U_0402_16V7K  [C_0402]  177.17 18.47 180 bottom
CS41  0.01U_0402_16V7K  [C_0402]  177.17 17.45 180 bottom
CS42  0.01U_0402_16V7K  [C_0402]  174.68 12.32 270 top
CV1  0.22U_0402_16V7K  [C_0402]  80.14 70.67 180 bottom
CV2  0.22U_0402_16V7K  [C_0402]  80.14 69.78 180 bottom
CV3  0.22U_0402_16V7K  [C_0402]  80.14 68.38 180 bottom
CV4  0.22U_0402_16V7K  [C_0402]  80.14 67.49 180 bottom
CV5  0.22U_0402_16V7K  [C_0402]  83.38 67.24 180 bottom
CV6  0.22U_0402_16V7K  [C_0402]  83.38 66.35 180 bottom
CV7  0.22U_0402_16V7K  [C_0402]  80.14 66.1 180 bottom
CV8  0.22U_0402_16V7K  [C_0402]  80.14 65.21 180 bottom
CV9  1000P_0402_50V7K  [C_0402]  53.02 107.65 270 bottom
CV10  0.1U_0402_16V4Z  [C_0402]  52.94 108.59 0 bottom
CV11  0.68U_0402_10V  [C_0402]  76.56 85.91 0 top
CV12  0.22U_0402_16V7K  [C_0402]  83.19 64.95 180 bottom
CV13  0.22U_0402_16V7K  [C_0402]  83.19 68.64 180 bottom
CV14  0.22U_0402_16V7K  [C_0402]  83.19 63.94 180 bottom
CV15  0.68U_0402_10V  [C_0402]  76.56 80.07 0 top
CV16  0.22U_0402_16V7K  [C_0402]  83.19 69.65 180 bottom
CV17  10P_0402_50V8J  [C_0402]  79.94 75.09 90 bottom
CV18  10P_0402_50V8J  [C_0402]  79 74.1 0 bottom
CV19  10U_0603_6.3V6M  [C_0603]  78.99 83.49 0 bottom
CV20  1U_0402_6.3V4Z  [C_0402]  79.23 81.21 0 bottom
CV21  0.1U_0402_10V6K  [C_0402]  79.23 82.22 0 bottom
CV22  0.1U_0402_25V6K  [C_0402]  74.43 90.35 180 top
CV26  1U_0402_6.3V4Z  [C_0402]  73.62 86.97 90 top
CV27  10U_0603_6.3V6M  [C_0603]  72.57 86.97 90 top
CV28  0.68U_0402_10V  [C_0402]  76.56 82.35 0 top
CV29  0.68U_0402_10V  [C_0402]  76.56 83.49 0 top
CV30  0.22U_0402_16V7K  [C_0402]  83.19 70.79 180 bottom
CV31  0.22U_0402_16V7K  [C_0402]  80.14 62.92 180 bottom
CV32  0.22U_0402_16V7K  [C_0402]  80.14 63.94 180 bottom
CV33  1U_0402_6.3V4Z  [C_0402]  71.18 84.08 270 top
CV34  0.1U_0402_10V6K  [C_0402]  70.29 84.08 270 top
CV35  0.22U_0402_16V7K  [C_0402]  83.19 71.81 180 bottom
CV38  10U_0603_6.3V6M  [C_0603]  75.32 75 180 top
CV39  0.1U_0402_10V6K  [C_0402]  78.97 73.72 0 top
CV40  2.2U_0402_6.3V6M  [C_0402]  59.01 86.82 270 top
CV41  2.2U_0402_6.3V6M  [C_0402]  58.6 80.7 0 top
CV42  2.2U_0402_6.3V6M  [C_0402]  57.26 85.53 0 top
CV43  10U_0603_6.3V6M  [C_0603]  27.81 78.41 180 top
CV44  10U_0603_6.3V6M  [C_0603]  27.81 79.68 180 top
CV45  10U_0603_6.3V6M  [C_0603]  27.81 80.95 180 top
CV46  1U_0402_6.3V4Z  [C_0402]  78.97 74.6 0 top
CV47  2.2U_0402_6.3V6M  [C_0402]  59.54 79.51 0 top
CV48  2.2U_0402_6.3V6M  [C_0402]  32.44 88.78 270 bottom
CV49  0.1U_0402_10V6K  [C_0402]  59.44 87.69 180 top
CV50  0.1U_0402_10V6K  [C_0402]  59.72 88.7 0 top
CV51  0.1U_0402_10V6K  [C_0402]  60.61 86.97 270 top
CV52  0.1U_0402_10V6K  [C_0402]  61.47 87 0 top
CV53  0.1U_0402_10V6K  [C_0402]  58.43 79.53 180 top
CV54  10U_0603_6.3V6M  [C_0603]  65.59 73.02 270 top
CV55  10U_0603_6.3V6M  [C_0603]  63.3 76.19 270 top
CV56  1U_0402_6.3V4Z  [C_0402]  72.98 74.3 90 top
CV57  1U_0402_6.3V4Z  [C_0402]  61.04 77.27 90 top
CV58  1U_0402_6.3V4Z  [C_0402]  61.02 75.75 180 top
CV59  1U_0402_6.3V4Z  [C_0402]  61.86 74.22 180 top
CV60  1U_0402_6.3V4Z  [C_0402]  59.77 77.63 90 top
CV61  10U_0603_6.3V6M  [C_0603]  73.53 77.27 0 top
CV62  1U_0402_6.3V4Z  [C_0402]  67.79 80.28 270 top
CV63  0.1U_0402_10V6K  [C_0402]  68.67 80.28 270 top
CV64  1U_0402_6.3V4Z  [C_0402]  68.51 83.27 0 top
CV65  1U_0402_6.3V4Z  [C_0402]  68.13 81.72 0 top
CV66  0.1U_0402_10V6K  [C_0402]  68.51 84.15 0 top
CV67  10U_0603_6.3V6M  [C_0603]  66.15 86.78 270 top
CV68  10U_0603_6.3V6M  [C_0603]  70.01 87.3 90 top
CV69  10U_0603_6.3V6M  [C_0603]  68.74 87.3 90 top
CV70  10U_0603_6.3V6M  [C_0603]  65.07 79.86 180 top
CV71  1U_0402_6.3V4Z  [C_0402]  63.2 87 0 top
CV72  1U_0402_6.3V4Z  [C_0402]  63.58 84.03 0 top
CV73  1U_0402_6.3V4Z  [C_0402]  62.41 82.22 270 top
CV74  1U_0402_6.3V4Z  [C_0402]  63.23 86.14 180 top
CV75  1U_0402_6.3V4Z  [C_0402]  64.41 82.26 90 top
CV76  1U_0402_6.3V4Z  [C_0402]  66.25 82.15 180 top
CV77  1U_0402_6.3V4Z  [C_0402]  64.09 85.22 90 top
CV78  1U_0402_6.3V4Z  [C_0402]  66.43 83.7 180 top
CV79  1U_0402_6.3V4Z  [C_0402]  63.54 81.43 0 top
CV80  1U_0402_6.3V4Z  [C_0402]  64.55 78.82 180 top
CV81  10U_0603_6.3V6M  [C_0603]  59.68 97.85 180 top
CV82  1U_0402_6.3V4Z  [C_0402]  60.97 95.51 180 top
CV83  10U_0603_6.3V6M  [C_0603]  60.97 96.55 180 top
CV84  10U_0603_6.3V6M  [C_0603]  56.57 95.88 90 top
CV85  1U_0402_6.3V4Z  [C_0402]  56.7 94.16 180 top
CV86  0.1U_0402_10V6K  [C_0402]  56.7 92.38 180 top
CV87  1U_0402_6.3V4Z  [C_0402]  61.47 85.22 90 top
CV88  10U_0603_6.3V6M  [C_0603]  60.42 83.67 0 top
CV89  1U_0402_6.3V4Z  [C_0402]  59.44 83.37 270 top
CV90  1U_0402_6.3V4Z  [C_0402]  59.37 84.18 90 top
CV91  10U_0603_6.3V6M  [C_0603]  58.82 94.19 0 top
CV92  1U_0402_6.3V4Z  [C_0402]  58.5 92.38 180 top
CV93  0.1U_0402_10V6K  [C_0402]  57.84 94.24 270 top
CV94  1U_0402_6.3V4Z  [C_0402]  56.44 68.18 90 top
CV95  1U_0402_6.3V4Z  [C_0402]  57.21 71.38 270 top
CV96  120P_0402_50V8J  [C_0402]  66.91 96.96 0 top
CV97  68P_0402_50V8J  [C_0402]  65.13 93.91 0 top
CV98  0.1U_0402_16V4Z  [C_0402]  63.73 96.52 270 top
CV99  0.1U_0402_16V4Z  [C_0402]  62.79 96.52 270 top
CV100  0.1U_0402_10V6K  [C_0402]  34.85 68.97 270 bottom
CV101  0.1U_0402_10V6K  [C_0402]  38.54 81.77 90 bottom
CV102  0.01U_0402_16V7K  [C_0402]  39.3 68.05 90 bottom
CV103  10U_0603_6.3V6M  [C_0603]  29.9 69.21 270 bottom
CV104  1U_0402_6.3V4Z  [C_0402]  31.17 68.97 270 bottom
CV105  1U_0402_6.3V4Z  [C_0402]  32.06 68.97 270 bottom
CV106  1U_0402_6.3V4Z  [C_0402]  40.19 68.97 270 bottom
CV107  1U_0402_6.3V4Z  [C_0402]  41.33 68.97 270 bottom
CV108  1U_0402_6.3V4Z  [C_0402]  29.6 81.72 180 bottom
CV109  1U_0402_6.3V4Z  [C_0402]  30.66 81.77 90 bottom
CV110  1U_0402_6.3V4Z  [C_0402]  31.68 81.77 90 bottom
CV111  0.1U_0402_10V6K  [C_0402]  32.7 81.77 90 bottom
CV112  0.1U_0402_10V6K  [C_0402]  41.59 81.77 90 bottom
CV113  0.1U_0402_10V6K  [C_0402]  42.6 81.77 90 bottom
CV114  0.1U_0402_10V6K  [C_0402]  33.71 81.77 90 bottom
CV115  0.1U_0402_10V6K  [C_0402]  40.57 81.77 90 bottom
CV116  0.1U_0402_10V6K  [C_0402]  34.73 81.77 90 bottom
CV117  0.1U_0402_10V6K  [C_0402]  35.74 81.77 90 bottom
CV118  10U_0603_6.3V6M  [C_0603]  29.9 69.21 270 top
CV119  1U_0402_6.3V4Z  [C_0402]  28.07 71.56 180 top
CV120  1U_0402_6.3V4Z  [C_0402]  31.17 68.97 270 top
CV121  1U_0402_6.3V4Z  [C_0402]  35.74 68.97 270 top
CV122  1U_0402_6.3V4Z  [C_0402]  40.19 68.97 270 top
CV123  1U_0402_6.3V4Z  [C_0402]  28.07 72.45 180 top
CV124  1U_0402_6.3V4Z  [C_0402]  38.41 68.71 270 top
CV125  1U_0402_6.3V4Z  [C_0402]  36.63 68.97 270 top
CV126  0.1U_0402_10V6K  [C_0402]  28.07 70.67 180 top
CV127  0.1U_0402_10V6K  [C_0402]  32.95 68.97 270 top
CV128  0.1U_0402_10V6K  [C_0402]  39.3 68.97 270 top
CV129  0.1U_0402_10V6K  [C_0402]  32.06 68.97 270 top
CV130  0.1U_0402_10V6K  [C_0402]  28.76 68.97 270 top
CV131  0.1U_0402_10V6K  [C_0402]  34.85 68.97 270 top
CV132  0.1U_0402_10V6K  [C_0402]  37.52 68.71 270 top
CV133  0.1U_0402_10V6K  [C_0402]  39.17 88.78 270 bottom
CV134  0.1U_0402_10V6K  [C_0402]  33.58 101.45 90 top
CV135  0.01U_0402_16V7K  [C_0402]  39.93 102.24 270 bottom
CV136  10U_0603_6.3V6M  [C_0603]  28.82 101.91 180 bottom
CV137  1U_0402_6.3V4Z  [C_0402]  42.6 101.45 90 bottom
CV138  1U_0402_6.3V4Z  [C_0402]  41.71 101.45 90 bottom
CV139  1U_0402_6.3V4Z  [C_0402]  37.27 101.32 90 bottom
CV140  1U_0402_6.3V4Z  [C_0402]  36.38 101.32 90 bottom
CV141  1U_0402_6.3V4Z  [C_0402]  31.93 101.45 90 bottom
CV142  1U_0402_6.3V4Z  [C_0402]  31.04 101.45 90 bottom
CV143  1U_0402_6.3V4Z  [C_0402]  33.71 101.45 90 bottom
CV144  0.1U_0402_10V6K  [C_0402]  40.82 101.45 90 bottom
CV145  0.1U_0402_10V6K  [C_0402]  34.47 88.83 270 bottom
CV146  0.1U_0402_10V6K  [C_0402]  36.25 88.78 270 bottom
CV147  0.1U_0402_10V6K  [C_0402]  35.36 88.83 270 bottom
CV148  0.1U_0402_10V6K  [C_0402]  30.03 101.45 90 bottom
CV149  0.1U_0402_10V6K  [C_0402]  32.82 101.45 90 bottom
CV150  0.1U_0402_10V6K  [C_0402]  43.49 101.45 90 bottom
CV151  10U_0603_6.3V6M  [C_0603]  28.19 101.66 180 top
CV152  1U_0402_6.3V4Z  [C_0402]  32.7 101.45 90 top
CV153  1U_0402_6.3V4Z  [C_0402]  38.16 101.58 90 top
CV154  1U_0402_6.3V4Z  [C_0402]  39.05 101.58 90 top
CV155  1U_0402_6.3V4Z  [C_0402]  37.27 101.45 90 top
CV156  1U_0402_6.3V4Z  [C_0402]  36.38 101.45 90 top
CV157  1U_0402_6.3V4Z  [C_0402]  39.93 101.58 90 top
CV158  1U_0402_6.3V4Z  [C_0402]  42.6 101.45 90 top
CV159  0.1U_0402_10V6K  [C_0402]  30.92 101.45 90 top
CV160  0.1U_0402_10V6K  [C_0402]  27.41 90.23 0 top
CV161  0.1U_0402_10V6K  [C_0402]  41.71 101.45 90 top
CV162  0.1U_0402_10V6K  [C_0402]  40.82 101.45 90 top
CV163  0.1U_0402_10V6K  [C_0402]  30.03 101.45 90 top
CV164  0.1U_0402_10V6K  [C_0402]  29.14 101.45 90 top
CV165  0.1U_0402_10V6K  [C_0402]  31.81 101.45 90 top
CV166  0.1U_0402_10V7K  [C_0402]  81.84 96.65 270 bottom
CV167  0.1U_0402_10V7K  [C_0402]  85.78 88.37 90 bottom
CV168  1U_0402_6.3V4Z  [C_0402]  61.32 79.05 0 top
CV169  10U_0603_6.3V6M  [C_0603]  85.78 92.07 270 bottom
CV170  0.1U_0402_10V7K  [C_0402]  81.72 88.37 90 bottom
CV171  0.1U_0402_10V6K  [C_0402]  32.95 68.97 270 bottom
CV172  1U_0402_6.3V4Z  [C_0402]  33.33 88.78 270 bottom
CV173  0.1U_0402_10V6K  [C_0402]  33.97 68.97 270 top
CV174  0.01U_0402_16V7K  [C_0402]  40.06 88.78 270 bottom
CV175  0.01U_0402_16V7K  [C_0402]  31.55 88.78 270 bottom
CV176  0.01U_0402_16V7K  [C_0402]  28.12 88.78 270 bottom
CV177  0.01U_0402_16V7K  [C_0402]  29.14 88.78 270 bottom
CV178  0.01U_0402_16V7K  [C_0402]  30.16 88.78 270 bottom
CV179  1U_0402_6.3V4Z  [C_0402]  28.07 73.33 180 top
CV180  0.1U_0402_10V6K  [C_0402]  43.49 101.45 90 top
CV181  1U_0402_6.3V4Z  [C_0402]  27.95 100.51 180 top
CV182  0.1U_0402_10V6K  [C_0402]  27.82 100.51 180 bottom
CV183  1U_0402_6.3V4Z  [C_0402]  27.82 99.62 180 bottom
CV184  0.1U_0402_16V7K  [C_0402]  124.26 113.01 90 bottom
CV185  0.1U_0402_16V7K  [C_0402]  123.25 113.01 90 bottom
CV186  0.1U_0402_16V7K  [C_0402]  122.36 115.29 90 bottom
CV187  0.1U_0402_16V7K  [C_0402]  121.34 115.29 90 bottom
CV188  0.1U_0402_16V7K  [C_0402]  120.83 113.01 90 bottom
CV189  0.1U_0402_16V7K  [C_0402]  119.82 113.01 90 bottom
CV190  0.1U_0402_16V7K  [C_0402]  118.55 115.29 90 bottom
CV191  0.1U_0402_16V7K  [C_0402]  117.53 115.29 90 bottom
CV357  1P_0402_50V8J  [C_0402]  197.08 86.8 0 top
CV358  1P_0402_50V8J  [C_0402]  197.08 82.22 0 top
CV359  1P_0402_50V8J  [C_0402]  197.08 85.78 0 top
CV360  1P_0402_50V8J  [C_0402]  197.08 83.24 0 top
CV361  1P_0402_50V8J  [C_0402]  197.08 89.34 0 top
CV362  1P_0402_50V8J  [C_0402]  196.78 78.62 270 top
CV363  1P_0402_50V8J  [C_0402]  196.78 79.73 90 top
CV364  1P_0402_50V8J  [C_0402]  197.08 90.35 0 top
CVT90  0.1U_0402_10V7K  [C_0402]  60.89 101.73 270 top
CX1  0.1U_0402_10V7K  [C_0402]  4.3 82.35 0 top
CX2  0.1U_0402_10V7K  [C_0402]  6.28 88.62 90 top
CX3  10U_0805_10V6K  [C_0805]  7.8 88.49 90 top
CX4  1000P_0402_50V7K  [C_0402]  10.34 76.59 270 top
CX5  0.1U_0603_25V7K  [C_0603]  6.09 78.67 0 top
CX7  4.7U_0805_10V4Z  [C_0805]  19.49 75.84 270 top
CX8  4.7U_0805_10V4Z  [C_0805]  8.31 86.63 270 top
CX11  0.1U_0402_10V7K  [C_0402]  9.33 88.62 90 top
CX12  0_0402_5%  [R0402_0OHM]  194.29 82.22 0 bottom
CX13  0_0402_5%  [R0402_0OHM]  194.29 83.24 0 bottom
CX14  0_0402_5%  [R0402_0OHM]  194.29 78.67 0 bottom
CX15  0_0402_5%  [R0402_0OHM]  194.29 79.68 0 bottom
CX16  0_0402_5%  [R0402_0OHM]  194.29 85.78 0 bottom
CX17  0_0402_5%  [R0402_0OHM]  194.29 86.8 0 bottom
CX18  0_0402_5%  [R0402_0OHM]  194.29 89.34 0 bottom
CX19  0_0402_5%  [R0402_0OHM]  194.29 90.35 0 bottom
CX20  220P_0402_50V8J  [C_0402]  198.25 73.08 180 top
CX21  0.1U_0402_16V7K  [C_0402]  199.57 82.02 90 top
CX22  10U_0603_6.3V6M  [C_0603]  199.51 80.7 180 top
CX23  1P_0402_50V8J  [C_0402]  199.83 82.43 270 bottom
CX24  1P_0402_50V8J  [C_0402]  199.83 83.29 90 bottom
CX25  1P_0402_50V8J  [C_0402]  199.83 78.87 270 bottom
CX26  1P_0402_50V8J  [C_0402]  199.83 79.73 90 bottom
CX27  1P_0402_50V8J  [C_0402]  199.83 85.98 270 bottom
CX28  1P_0402_50V8J  [C_0402]  199.83 86.85 90 bottom
CX29  1P_0402_50V8J  [C_0402]  199.83 89.54 270 bottom
CX30  1P_0402_50V8J  [C_0402]  199.83 90.4 90 bottom
CX31  10P_0402_50V8J  [C_0402]  14.15 86.75 270 top
CX49  4.7U_0805_10V4Z  [C_0805]  11.36 96.11 90 top
CX50  0.1U_0402_10V7K  [C_0402]  9.84 96.24 90 top
CZ1  1U_0603_10V6K  [C_0603]  70.73 31.81 180 top
CZ2  1U_0603_10V6K  [C_0603]  76.13 31.74 90 top
CZ3  10U_0805_10V_X5R  [C_0805]  70.03 35.65 90 top
CZ4  1U_0603_10V6K  [C_0603]  71.56 35.55 90 top
CZ5  0.1U_0402_16V7K  [C_0402]  74.35 29.85 270 top
CZ9  1000P_0402_50V7K  [C_0402]  72.83 35.54 90 top
CZ13  10U_0805_10V_X5R  [C_0805]  76.64 35.65 90 top
CZ14  1U_0603_10V6K  [C_0603]  75.11 35.55 90 top
CZ15  470P_0402_50V7K  [C_0402]  73.84 35.54 90 top
D6  RB751V-40_SOD-323  [RB751V40_SC76-2]  165.75 5.01 180 top
D7  RB751V-40_SOD-323  [RB751V40_SC76-2]  165.75 6.66 180 top
D29  -  [DB2J31400L_SOD323-2]  99.84 87.56 0 top
D30  -  [DB2J31400L_SOD323-2]  99.72 83.37 0 top
DA8  -  [BAT54C-7-F_SOT23-3]  190.65 17.2 90 top
DA10  AZ5125-02S.R7G_SOT23-3  [AZ5125-02SPR7G_SOT23-3]  197.19 28.25 270 bottom
DA12  AZ5125-02S.R7G_SOT23-3  [AZ5125-02SPR7G_SOT23-3]  197.19 32.19 270 bottom
DA13  AZ5125-02S.R7G_SOT23-3  [AZ5125-02SPR7G_SOT23-3]  204.4 16.92 180 bottom
DA14  AZ5125-02S.R7G_SOT23-3  [AZ5125-02SPR7G_SOT23-3]  209.48 16.92 180 bottom
DE2  -  [L03ESDL5V0CC3-2_SOT23-3]  173.13 119.56 90 bottom
DH1  RB751V-40_SOD-323  [RB751V40_SC76-2]  147.3 4.52 270 top
DH2  RB751V-40_SOD-323  [RB751V40_SC76-2]  149.01 4.52 270 top
DI1  IP4292CZ10-TBR_XSON10_2.5X1  [IP4292CZ10-TBR_XSON10_2P5X1]  196.76 64.15 180 bottom
DI2  -  [L30ESDL5V0C3-2_SOT23-3]  195.26 67.01 180 top
DI4  IP4292CZ10-TBR_XSON10_2.5X1  [IP4292CZ10-TBR_XSON10_2P5X1]  194.03 47.92 270 bottom
DI5  -  [L30ESDL5V0C3-2_SOT23-3]  194.27 43.36 270 bottom
DX1  -  [RB751V-40_SOD323-2]  6.48 80.19 0 top
DX2  -  [PESD5V0U2BT_SOT23-3]  5.49 92.89 270 top
FD1  FIDUCAL  [FIDUCIAL_C40M80]  205.54 3.48 180 bottom
FD2  FIDUCIAL  [FIDUCIAL_C40M80]  208.72 3.48 0 top
FD3  FIDUCAL  [FIDUCIAL_C40M80]  14.15 107.88 180 bottom
FD4  FIDUCIAL  [FIDUCIAL_C40M80]  14.15 107.88 0 top
FE1  0.75A_24V_1812L075-24DR~OK  [F_1812L075-24DR]  131.37 12.74 90 top
FX1  1.5A_6V_1206L150PR  [F_1206L150PR]  198.81 79.31 270 top
H1  -  [H_2P8N]  206.4 74.8 0 top
H2  -  [H_2P8]  198.4 118.8 0 top
H3  -  [H_2P8]  195.5 96.4 0 top
H4  -  [H_2P8]  183 32.1 90 top
H5  -  [H_2P8]  195 4 0 top
H6  -  [H_2P8]  101 3.5 0 top
H7  -  [H_2P8]  21.8 9.8 0 top
H8  -  [H_2P8]  82.8 57.8 0 top
H9  -  [H_2P8]  27.8 118.8 0 top
H11  -  [H_2P8]  22.1 92.1 0 top
H12  -  [H_2P8]  165.8 69.8 0 top
H13  -  [H_3P6]  160.1 82 0 top
H14  -  [H_3P6]  115.1 107.4 0 top
H15  -  [H_3P6]  115.1 82 0 top
H16  -  [H_3P6]  160.1 107.4 0 top
H17  -  [H_3P3]  86.33 106.83 0 top
H18  -  [H_3P3]  41.67 60.57 0 top
H19  -  [H_3P3]  181.73 91.35 0 top
H20  -  [H_2P8N]  195 10 0 top
H21  -  [H_2P8N]  204.4 118.8 0 top
H22  -  [H_2P8X3P3N]  34.04 118.85 90 top
H23  -  [H_2P8X4P8N]  208.31 22.28 90 top
HE1  100K_0402_1%_TSM0B104F4251RZ  [R_0402]  14.03 64.49 90 bottom
J11  -  [JUMP_43X118]  126.88 7.71 90 top
